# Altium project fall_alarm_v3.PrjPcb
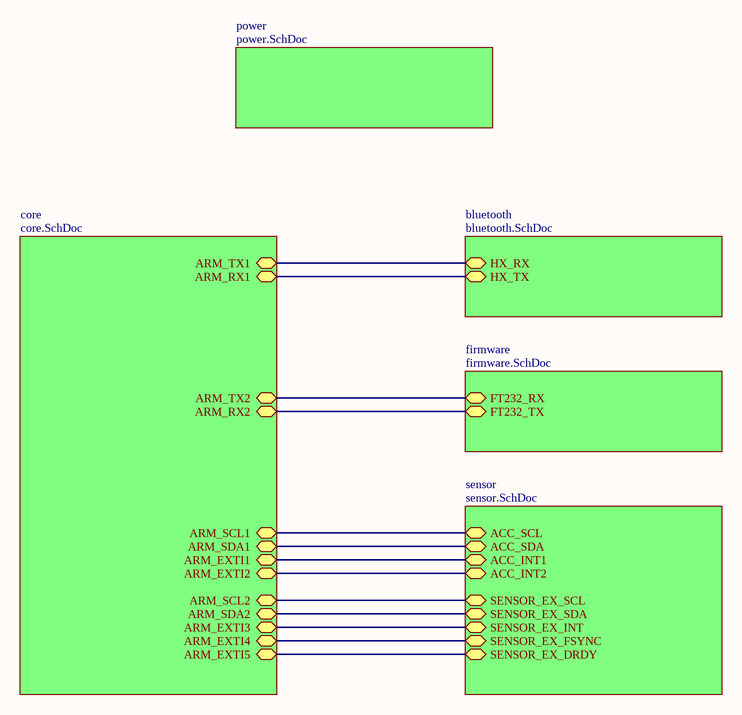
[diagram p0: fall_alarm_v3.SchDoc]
6 sheets, 67 parts. Net scope: hierarchical (ports join the sheet entries above them; power ports are global).
Board file: fall_alarm_v3.PcbDoc
Sheets:
  fall_alarm_v3.SchDoc
    core = core.SchDoc
    bluetooth = bluetooth.SchDoc
    firmware = firmware.SchDoc
    power = power.SchDoc
    sensor = sensor.SchDoc

## Sheet fall_alarm_v3.SchDoc
size A4

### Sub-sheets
bluetooth = bluetooth.SchDoc: HX_RX (bidir), HX_TX (bidir)
core = core.SchDoc: ARM_TX1 (bidir), ARM_RX1 (bidir), ARM_TX2 (bidir), ARM_RX2 (bidir), ARM_SCL1 (bidir), ARM_SDA1 (bidir), ARM_EXTI1 (bidir), ARM_EXTI2 (bidir), ARM_SCL2 (bidir), ARM_SDA2 (bidir), ARM_EXTI3 (bidir), ARM_EXTI4 (bidir), ARM_EXTI5 (bidir)
firmware = firmware.SchDoc: FT232_RX (bidir), FT232_TX (bidir)
power = power.SchDoc: no entries
sensor = sensor.SchDoc: ACC_SCL (bidir), ACC_SDA (bidir), ACC_INT1 (bidir), ACC_INT2 (bidir), SENSOR_EX_SCL (bidir), SENSOR_EX_SDA (bidir), SENSOR_EX_INT (bidir), SENSOR_EX_FSYNC (bidir), SENSOR_EX_DRDY (bidir)

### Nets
NetP11_2: sheet core/ARM_RX2, sheet firmware/FT232_TX
NetP11_4: sheet core/ARM_TX2, sheet firmware/FT232_RX
NetP41_1: sheet core/ARM_EXTI5, sheet sensor/SENSOR_EX_DRDY
NetP41_2: sheet core/ARM_EXTI4, sheet sensor/SENSOR_EX_FSYNC
NetP41_3: sheet core/ARM_EXTI3, sheet sensor/SENSOR_EX_INT
NetP41_4: sheet core/ARM_SCL2, sheet sensor/SENSOR_EX_SCL
NetP41_5: sheet core/ARM_SDA2, sheet sensor/SENSOR_EX_SDA
NetR42_2: sheet core/ARM_SCL1, sheet sensor/ACC_SCL
NetR43_2: sheet core/ARM_SDA1, sheet sensor/ACC_SDA
NetU1_29: sheet core/ARM_EXTI2, sheet sensor/ACC_INT2
NetU1_30: sheet core/ARM_TX1, sheet bluetooth/HX_RX
NetU1_31: sheet core/ARM_RX1, sheet bluetooth/HX_TX
NetU1_32: sheet core/ARM_EXTI1, sheet sensor/ACC_INT1

## Sheet core.SchDoc
size A4
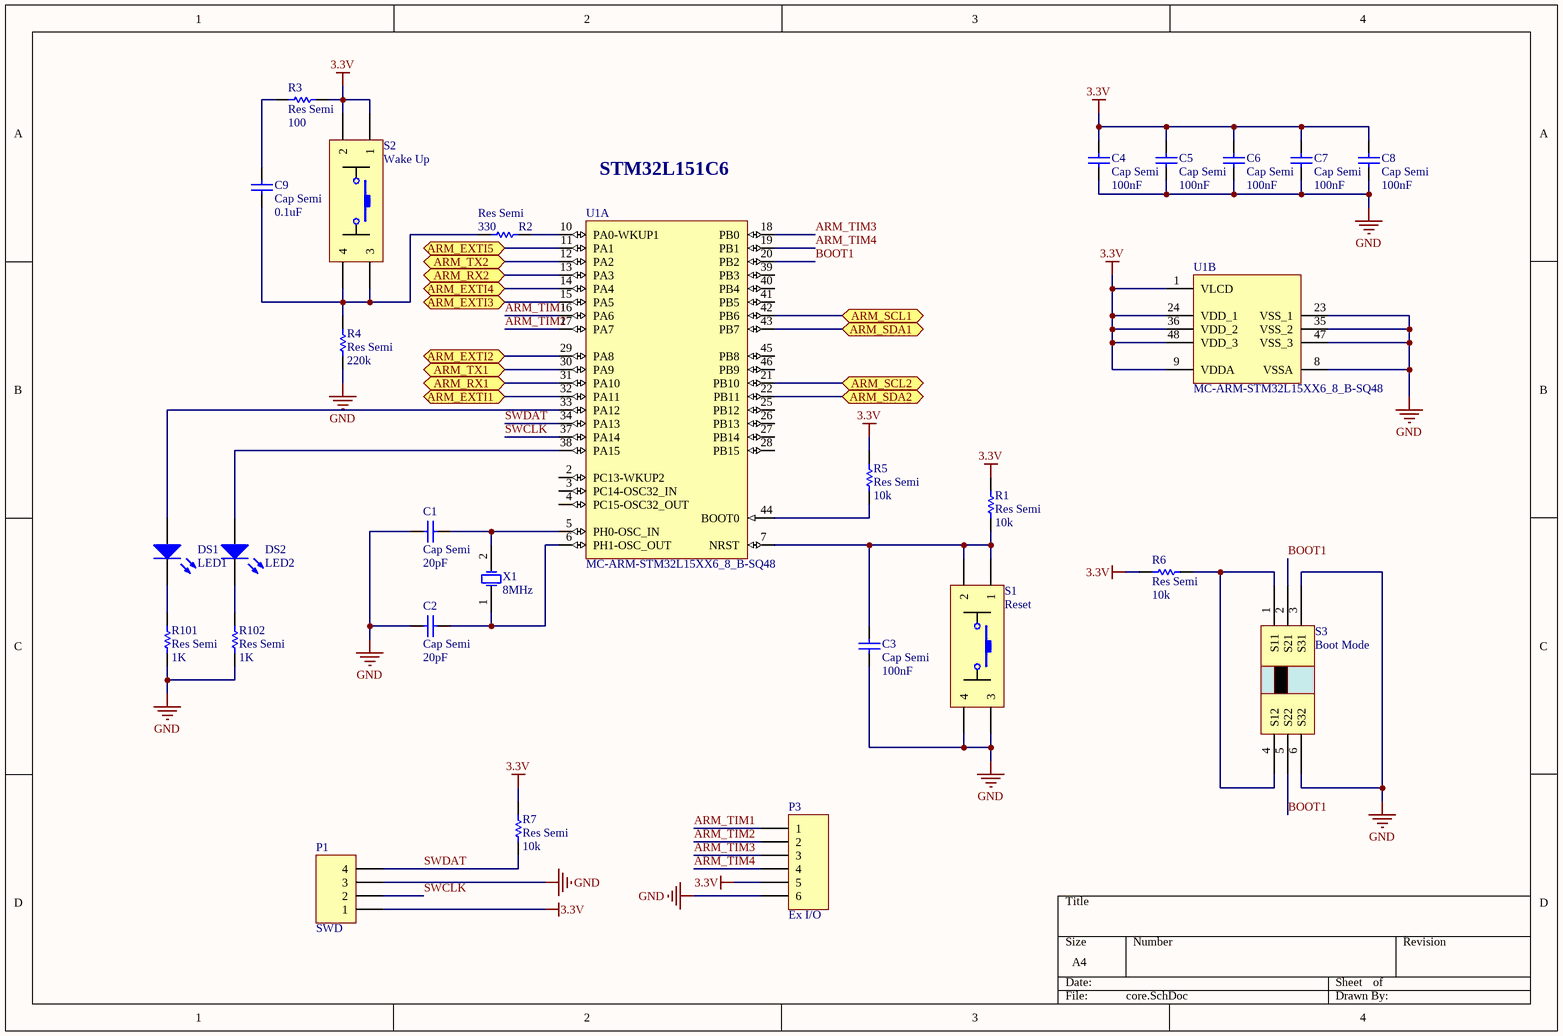
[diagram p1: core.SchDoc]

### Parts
C1  Cap Semi  value 20pF  [C1608-0603]
C2  Cap Semi  value 20pF  [C1608-0603]
C3  Cap Semi  value 100nF  [C1608-0603]
C4  Cap Semi  value 100nF  [C1608-0603]
C5  Cap Semi  value 100nF  [C1608-0603]
C6  Cap Semi  value 100nF  [C1608-0603]
C7  Cap Semi  value 100nF  [C1608-0603]
C8  Cap Semi  value 100nF  [C1608-0603]
C9  Cap Semi  value 0.1uF  [C1608-0603]
DS1  LED1  [LED0603_AB]
DS2  LED2  [LED0603_AB]
P1  SWD  [HDR1X4H]
P3  Ex I/O  [HDR1X6H]
R1  Res Semi  value 10k  [R1608-0603]
R2  Res Semi  value 330  [R1608-0603]
R3  Res Semi  value 100  [R1608-0603]
R4  Res Semi  value 220k  [R1608-0603]
R5  Res Semi  value 10k  [R1608-0603]
R6  Res Semi  value 10k  [R1608-0603]
R7  Res Semi  value 10k  [R1608-0603]
R101  Res Semi  value 1K  [R1608-0603]
R102  Res Semi  value 1K  [R1608-0603]
S1  Reset  [Switch6X6]
S2  Wake Up  [Switch6X6]
S3  Boot Mode  [SWITCH_6]
U1  MC-ARM-STM32L15XX6_8_B-SQ48  [STM-LQFP48_N]  (parts A,B of 2)
X1  8MHz  [XTAL-0.2]

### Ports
ARM_EXTI1 (bidir), ARM_EXTI2 (bidir), ARM_EXTI3 (bidir), ARM_EXTI4 (bidir), ARM_EXTI5 (bidir), ARM_RX1 (bidir), ARM_RX2 (bidir), ARM_SCL1 (bidir), ARM_SCL2 (bidir), ARM_SDA1 (bidir), ARM_SDA2 (bidir), ARM_TX1 (bidir), ARM_TX2 (bidir)

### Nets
3.3V: C4.1 C5.1 C6.1 C7.1 C8.1 P1.1 P3.5 R1.1 R3.1 R5.1 R6.1 R7.1 S2.1 S2.2 U1.1(VLCD) U1.9(VDDA) U1.24(VDD_1) U1.36(VDD_2) U1.48(VDD_3)
GND: C1.2 C2.2 C3.2 C4.2 C5.2 C6.2 C7.2 C8.2 P1.3 P3.6 R4.1 R101.2 R102.2 S1.3 S1.4 S3.3(S31) S3.6(S32) U1.8(VSSA) U1.23(VSS_1) U1.35(VSS_2) U1.47(VSS_3)
ARM_TIM1: P3.1 U1.16(PA6)
ARM_TIM2: P3.2 U1.17(PA7)
ARM_TIM3: P3.3 U1.18(PB0)
ARM_TIM4: P3.4 U1.19(PB1)
BOOT1: S3.2(S21) S3.5(S22) U1.20(PB2)
SWCLK: P1.2 U1.37(PA14)
SWDAT: P1.4 R7.2 U1.34(PA13)
NetC1_1: C1.1 U1.5(PH0-OSC_IN) X1.2(OSC2)
NetC2_1: C2.1 U1.6(PH1-OSC_OUT) X1.1(OSC1)
NetC3_1: C3.1 R1.2 S1.1 S1.2 U1.7(NRST)
NetC9_1: C9.1 R3.2
NetC9_2: C9.2 R2.2 R4.2 S2.3 S2.4
NetDS1_1: DS1.1(A) U1.33(PA12)
NetDS1_2: DS1.2(K) R101.1
NetDS2_1: DS2.1(A) U1.38(PA15)
NetDS2_2: DS2.2(K) R102.1
NetP11_2: U1.13(PA3) ; port ARM_RX2
NetP11_4: U1.12(PA2) ; port ARM_TX2
NetP41_1: U1.11(PA1) ; port ARM_EXTI5
NetP41_2: U1.14(PA4) ; port ARM_EXTI4
NetP41_3: U1.15(PA5) ; port ARM_EXTI3
NetP41_4: U1.21(PB10) ; port ARM_SCL2
NetP41_5: U1.22(PB11) ; port ARM_SDA2
NetR2_1: R2.1 U1.10(PA0-WKUP1)
NetR5_2: R5.2 U1.44(BOOT0)
NetR6_2: R6.2 S3.1(S11) S3.4(S12)
NetR42_2: U1.42(PB6) ; port ARM_SCL1
NetR43_2: U1.43(PB7) ; port ARM_SDA1
NetU1_29: U1.29(PA8) ; port ARM_EXTI2
NetU1_30: U1.30(PA9) ; port ARM_TX1
NetU1_31: U1.31(PA10) ; port ARM_RX1
NetU1_32: U1.32(PA11) ; port ARM_EXTI1

Not connected (* = marked no-connect by the designer): U1 2(PC13-WKUP2) 3(PC14-OSC32_IN) 4(PC15-OSC32_OUT) 25(PB12) 26(PB13) 27(PB14) 28(PB15) 39(PB3) 40(PB4) 41(PB5) 45(PB8) 46(PB9)

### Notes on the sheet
- STM32L151C6

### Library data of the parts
C1-C9 = Cap Semi: Capacitor (Semiconductor SIM Model)
DS1 DS2 = LED3: Typical BLUE SiC LED
P1 = Header 4H: Header, 4-Pin, Right Angle
P3 = Header 6H: Header, 6-Pin, Right Angle
R1-R7 R101 R102 = Res Semi: Semiconductor Resistor
S1 S2 = Switch6X6: Switch
S3 = SWITCH_6
X1 = XTAL: Crystal Oscillator

## Sheet bluetooth.SchDoc
size A4
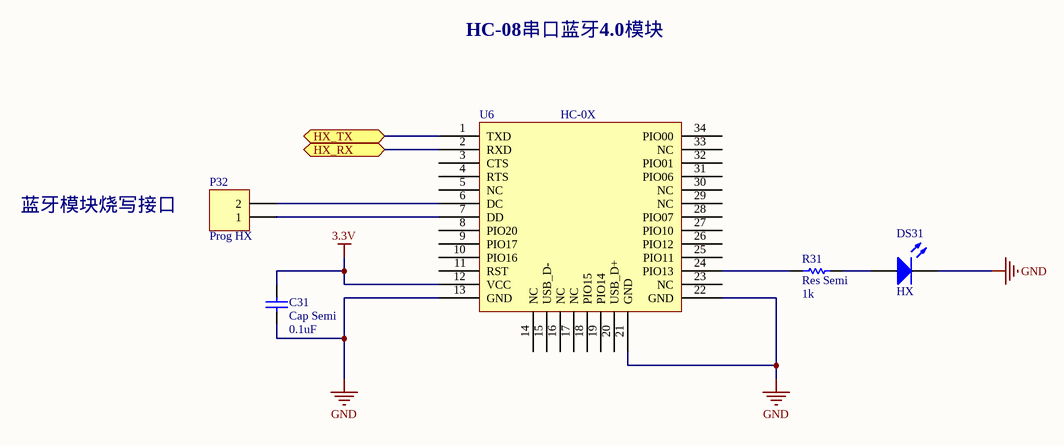
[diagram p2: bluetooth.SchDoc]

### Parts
C31  Cap Semi  value 0.1uF  [C1608-0603]
DS31  HX  [LED0603_AB]
P32  Prog HX  [HDR1X2]
R31  Res Semi  value 1k  [R1608-0603]
U6  HC-0X  [HC-0X_4]

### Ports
HX_RX (bidir), HX_TX (bidir)

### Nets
3.3V: C31.1 U6.12(VCC)
GND: C31.2 DS31.2(K) U6.13(GND) U6.21(GND) U6.22(GND)
NetDS31_1: DS31.1(A) R31.2
NetP32_1: P32.1 U6.7(DD)
NetP32_2: P32.2 U6.6(DC)
NetR31_1: R31.1 U6.24(PIO13)
NetU1_30: U6.2(RXD) ; port HX_RX
NetU1_31: U6.1(TXD) ; port HX_TX

Not connected (* = marked no-connect by the designer): U6 3(CTS) 4(RTS) 5(NC) 8(PIO20) 9(PIO17) 10(PIO16) 11(RST) 14(NC) 15(USB_D-) 16(NC) 17(NC) 18(PIO15) 19(PIO14) 20(USB_D+) 23(NC) 25(PIO11) 26(PIO12) 27(PIO10) 28(PIO07) 29(NC) 30(NC) 31(PIO06) 32(PIO01) 33(NC) 34(PIO00)

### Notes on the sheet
- HC-08串口蓝牙4.0模块
- 蓝牙模块烧写接口

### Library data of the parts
C31 = Cap Semi: Capacitor (Semiconductor SIM Model)
DS31 = LED3: Typical BLUE SiC LED
P32 = Header 2: Header, 2-Pin
R31 = Res Semi: Semiconductor Resistor

## Sheet firmware.SchDoc
size A4
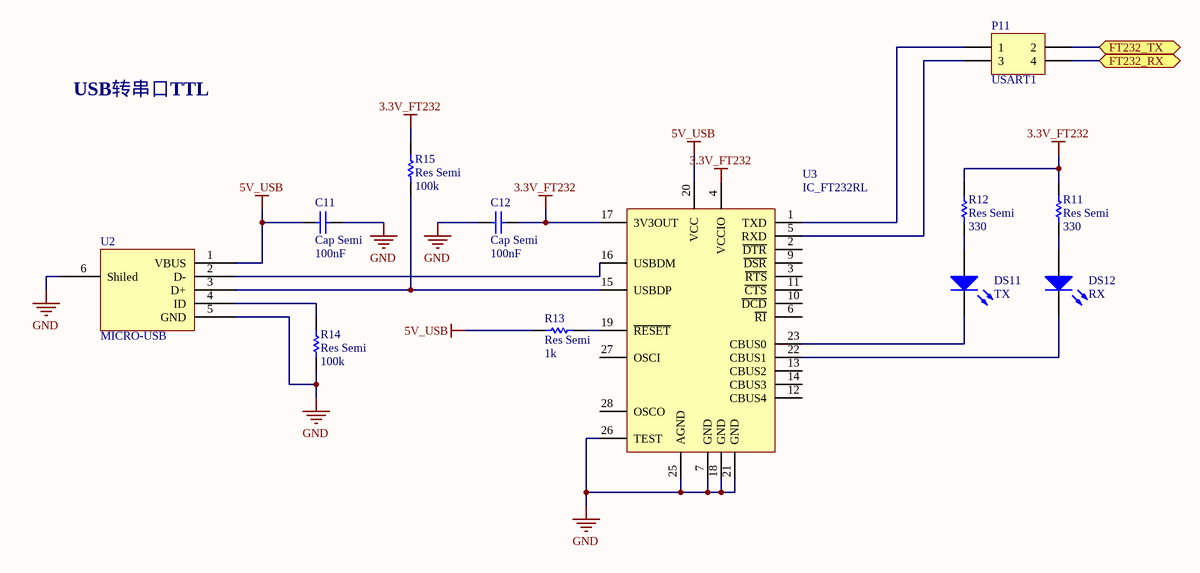
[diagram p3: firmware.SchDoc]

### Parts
C11  Cap Semi  value 100nF  [C1608-0603]
C12  Cap Semi  value 100nF  [C1608-0603]
DS11  TX  [LED0603_AB]
DS12  RX  [LED0603_AB]
P11  USART1  [HDR2X2]
R11  Res Semi  value 330  [R1608-0603]
R12  Res Semi  value 330  [R1608-0603]
R13  Res Semi  value 1k  [R1608-0603]
R14  Res Semi  value 100k  [R1608-0603]
R15  Res Semi  value 100k  [R1608-0603]
U2  MICRO-USB  [MICRO-USB]
U3  IC_FT232RL  [SSOP-28]

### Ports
FT232_RX (bidir), FT232_TX (bidir)

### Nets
3.3V_FT232: C12.2 R11.1 R12.1 R15.1 U3.4(VCCIO) U3.17(3V3OUT)
5V_USB: C11.1 R13.1 U2.1(VBUS) U3.20(VCC)
GND: C11.2 C12.1 R14.2 U2.5(GND) U2.6(Shiled) U3.7(GND) U3.18(GND) U3.21(GND) U3.25(AGND) U3.26(TEST)
NC: U3.8(NC) U3.24(NC)
NetDS11_1: DS11.1(A) R12.2
NetDS11_2: DS11.2(K) U3.23(CBUS0)
NetDS12_1: DS12.1(A) R11.2
NetDS12_2: DS12.2(K) U3.22(CBUS1)
NetP11_1: P11.1 U3.1(TXD)
NetP11_2: P11.2 ; port FT232_TX
NetP11_3: P11.3 U3.5(RXD)
NetP11_4: P11.4 ; port FT232_RX
NetR13_2: R13.2 U3.19(~{RESET})
NetR14_1: R14.1 U2.4(ID)
NetR15_2: R15.2 U2.3(D+) U3.15(USBDP)
NetU2_2: U2.2(D-) U3.16(USBDM)

Not connected (* = marked no-connect by the designer): U3 2(~{DTR}) 3(~{RTS}) 6(~{RI}) 9(~{DSR}) 10(~{DCD}) 11(~{CTS}) 12(CBUS4) 13(CBUS2) 14(CBUS3) 27(OSCI) 28(OSCO)

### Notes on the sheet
- USB转串口TTL

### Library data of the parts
C11 C12 = Cap Semi: Capacitor (Semiconductor SIM Model)
DS11 DS12 = LED3: Typical BLUE SiC LED
P11 = Header 2X2: Header, 2-Pin, Dual row
R11-R15 = Res Semi: Semiconductor Resistor
U3 = IC_FT232RL: FT232R USB UART

## Sheet power.SchDoc
size A4
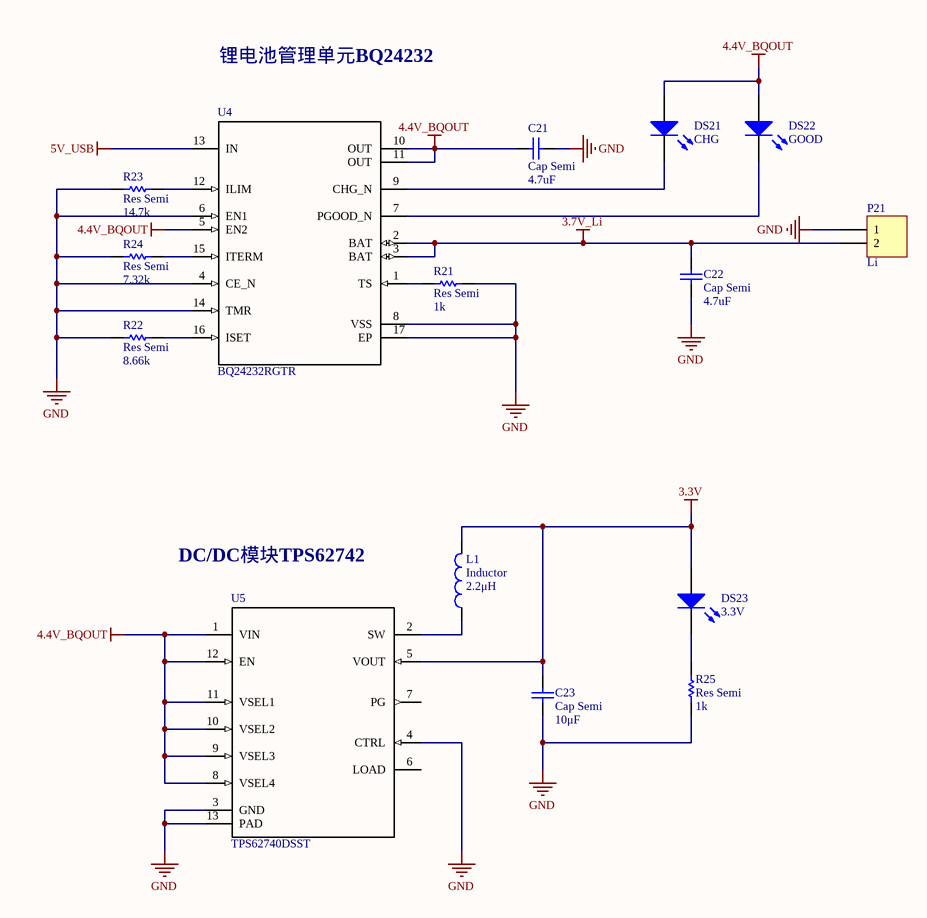
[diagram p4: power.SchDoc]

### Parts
C21  Cap Semi  value 4.7uF  [C1608-0603]
C22  Cap Semi  value 4.7uF  [C1608-0603]
C23  Cap Semi  value 10μF  [C1608-0603]
DS21  CHG  [LED0603_AB]
DS22  GOOD  [LED0603_AB]
DS23  3.3V  [LED0603_AB]
L1  Inductor  value 2.2μH  [I1608-0603]
P21  Li  [HDR1X2]
R21  Res Semi  value 1k  [R1608-0603]
R22  Res Semi  value 8.66k  [R1608-0603]
R23  Res Semi  value 14.7k  [R1608-0603]
R24  Res Semi  value 7.32k  [R1608-0603]
R25  Res Semi  value 1k  [R1608-0603]
U4  BQ24232RGTR  [RGT0016C]
U5  TPS62740DSST  [DSS0012A]

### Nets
3.3V: C23.1 DS23.1(A) L1.2 U5.5(VOUT)
3.7V_Li: C22.2 P21.2 U4.2(BAT) U4.3(BAT)
4.4V_BQOUT: C21.2 DS21.1(A) DS22.1(A) U4.5(EN2) U4.10(OUT) U4.11(OUT) U5.1(VIN) U5.8(VSEL4) U5.9(VSEL3) U5.10(VSEL2) U5.11(VSEL1) U5.12(EN)
5V_USB: U4.13(IN)
GND: C21.1 C22.1 C23.2 P21.1 R21.2 R22.1 R23.1 R24.1 R25.1 U4.4(CE_N) U4.6(EN1) U4.8(VSS) U4.14(TMR) U4.17(EP) U5.3(GND) U5.4(CTRL) U5.13(PAD)
NetDS21_2: DS21.2(K) U4.9(CHG_N)
NetDS22_2: DS22.2(K) U4.7(PGOOD_N)
NetDS23_2: DS23.2(K) R25.2
NetL1_1: L1.1 U5.2(SW)
NetR21_1: R21.1 U4.1(TS)
NetR22_2: R22.2 U4.16(ISET)
NetR23_2: R23.2 U4.12(ILIM)
NetR24_2: R24.2 U4.15(ITERM)

Not connected (* = marked no-connect by the designer): U5 6(LOAD) 7(PG)

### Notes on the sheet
- 锂电池管理单元BQ24232
- DC/DC模块TPS62742

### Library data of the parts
C21-C23 = Cap Semi: Capacitor (Semiconductor SIM Model)
DS21-DS23 = LED3: Typical BLUE SiC LED
L1 = Inductor: Code_IEC: 1005
P21 = Header 2: Header, 2-Pin
R21-R25 = Res Semi: Semiconductor Resistor
U4 = BQ24232RGTR: Imported; Alternate PartNumber: BQ24232RGTT; Manufacturer: Texas Instruments; CompType: IC; PIN_COUNT: 17
U5 = TPS62740DSST: Imported; Alternate Manufacturer: None; Manufacturer: Texas Instruments; CurrentTime: Not shown in title block; DocumentNumber: 1; SymbolCreator: a0411947; CompType: IC; U/M: EA; Designator: U?; PIN_COUNT: 13

## Sheet sensor.SchDoc
size A4
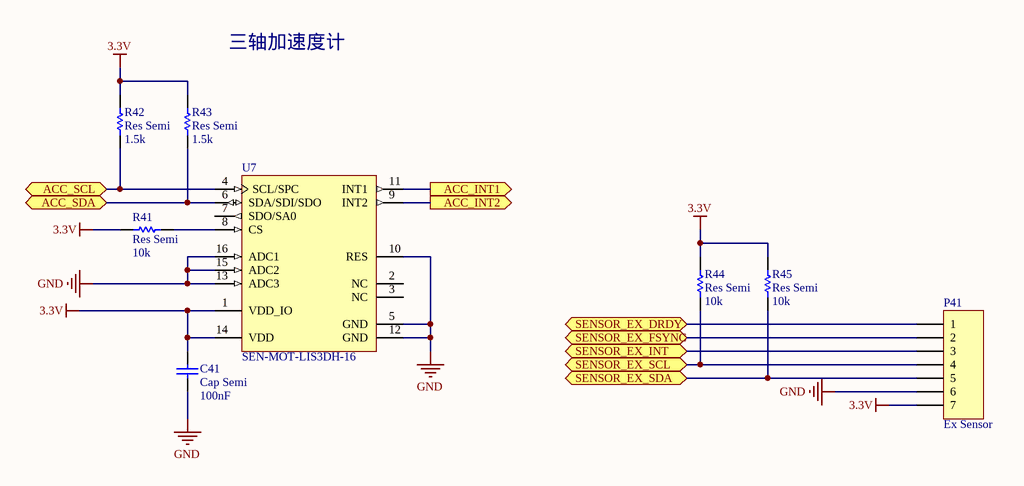
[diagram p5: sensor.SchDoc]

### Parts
C41  Cap Semi  value 100nF  [C1608-0603]
P41  Ex Sensor  [HDR1X7H]
R41  Res Semi  value 10k  [R1608-0603]
R42  Res Semi  value 1.5k  [R1608-0603]
R43  Res Semi  value 1.5k  [R1608-0603]
R44  Res Semi  value 10k  [R1608-0603]
R45  Res Semi  value 10k  [R1608-0603]
U7  SEN-MOT-LIS3DH-16  [LGA16-3X3X1_M]

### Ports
ACC_INT1 (out), ACC_INT2 (out), ACC_SCL (bidir), ACC_SDA (bidir), SENSOR_EX_DRDY (bidir), SENSOR_EX_FSYNC (bidir), SENSOR_EX_INT (bidir), SENSOR_EX_SCL (bidir), SENSOR_EX_SDA (bidir)

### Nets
3.3V: C41.1 P41.7 R41.1 R42.1 R43.1 R44.1 R45.1 U7.1(VDD_IO) U7.14(VDD)
GND: C41.2 P41.6 U7.5(GND) U7.10(RES) U7.12(GND) U7.13(ADC3) U7.15(ADC2) U7.16(ADC1)
NetP41_1: P41.1 ; port SENSOR_EX_DRDY
NetP41_2: P41.2 ; port SENSOR_EX_FSYNC
NetP41_3: P41.3 ; port SENSOR_EX_INT
NetP41_4: P41.4 R44.2 ; port SENSOR_EX_SCL
NetP41_5: P41.5 R45.2 ; port SENSOR_EX_SDA
NetR41_2: R41.2 U7.8(CS)
NetR42_2: R42.2 U7.4(SCL/SPC) ; port ACC_SCL
NetR43_2: R43.2 U7.6(SDA/SDI/SDO) ; port ACC_SDA
NetU1_29: U7.9(INT2) ; port ACC_INT2
NetU1_32: U7.11(INT1) ; port ACC_INT1

Not connected (* = marked no-connect by the designer): U7 2(NC) 3(NC) 7(SDO/SA0)

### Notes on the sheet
- 三轴加速度计

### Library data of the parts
C41 = Cap Semi: Capacitor (Semiconductor SIM Model)
P41 = Header 7H: Header, 7-Pin, Right Angle
R41-R45 = Res Semi: Semiconductor Resistor

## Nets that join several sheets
3.3V: core (19 pins), bluetooth (C31.1 U6.12), power (C23.1 DS23.1 L1.2 U5.5), sensor (9 pins)
5V_USB: firmware (C11.1 R13.1 U2.1 U3.20), power (U4.13)
GND: core (21 pins), bluetooth (5 pins), firmware (10 pins), power (17 pins), sensor (8 pins)
NetP11_2: core (U1.13), firmware (P11.2)
NetP11_4: core (U1.12), firmware (P11.4)
NetP41_1: core (U1.11), sensor (P41.1)
NetP41_2: core (U1.14), sensor (P41.2)
NetP41_3: core (U1.15), sensor (P41.3)
NetP41_4: core (U1.21), sensor (P41.4 R44.2)
NetP41_5: core (U1.22), sensor (P41.5 R45.2)
NetR42_2: core (U1.42), sensor (R42.2 U7.4)
NetR43_2: core (U1.43), sensor (R43.2 U7.6)
NetU1_29: core (U1.29), sensor (U7.9)
NetU1_30: core (U1.30), bluetooth (U6.2)
NetU1_31: core (U1.31), bluetooth (U6.1)
NetU1_32: core (U1.32), sensor (U7.11)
